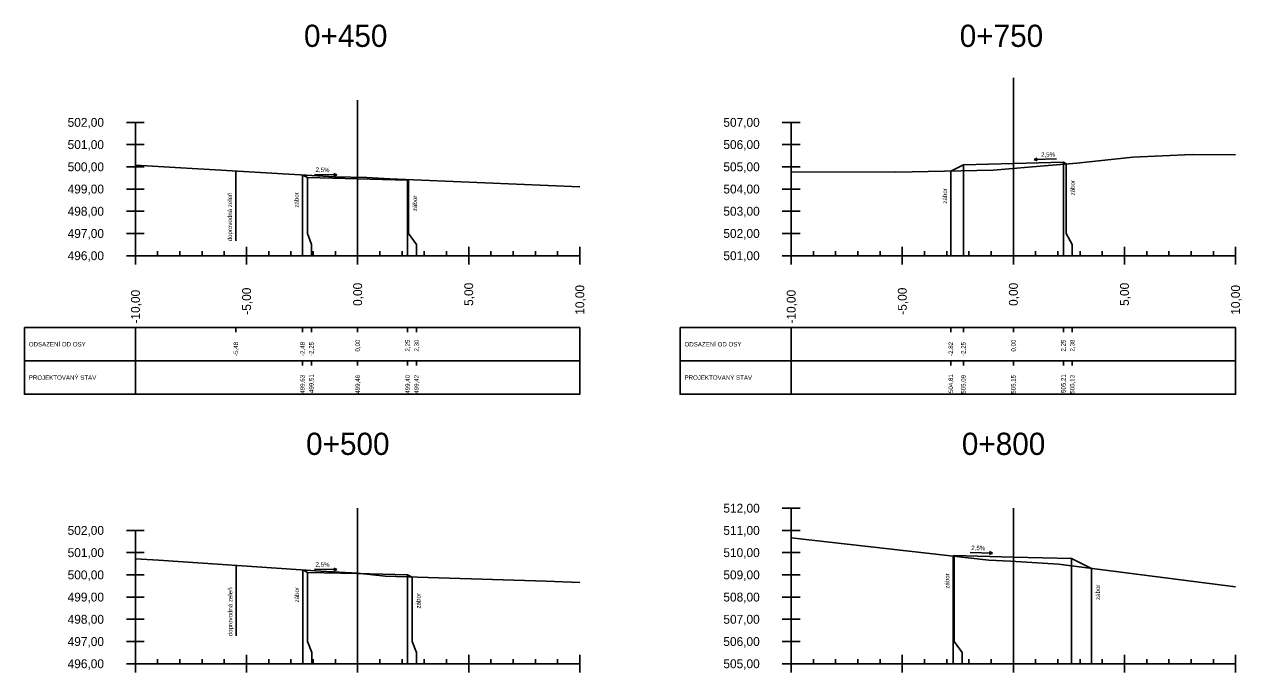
# Model space of a CAD drawing. Extents: x -631407 to -631215, y -1089700 to -1088598.
# Drawn here: x -631373.7 to -631319, y -1089386.7 to -1089357.5 of the extents above; entities that cross this region are included whole.
import ezdxf

# ---------------------------------------------------------------- set-up
doc = ezdxf.new("R2010")
doc.units = 0
for name, color, linetype in [('59', 7, 'Continuous'), ('NIVELETA_VYSKY', 7, 'Continuous'), ('REZ_BODY', 7, 'Continuous'), ('REZ_ODSTUPY', 7, 'Continuous'), ('REZ_POPIS', 7, 'Continuous'), ('REZ_RAMY', 7, 'Continuous'), ('REZ_STANICENI', 7, 'Continuous'), ('REZ_SVISLE', 7, 'Continuous'), ('REZ_TENKA', 7, 'Continuous'), ('REZ_TLUSTA', 7, 'Continuous'), ('TABULKA_POPIS', 7, 'Continuous'), ('TEREN', 7, 'Continuous'), ('zábor', 7, 'Continuous')]:
    doc.layers.add(name, color=color, linetype=linetype)

msp = doc.modelspace()

# ---------------------------------------------------------------- linework, layer by layer
at = {"layer": '59'}
for p, q in [((-631369.144, -1089361.911), (-631368.344, -1089361.911)), ((-631368.744, -1089361.911), (-631368.744, -1089367.911)), ((-631339.63, -1089361.911), (-631338.83, -1089361.911)), ((-631339.23, -1089361.911), (-631339.23, -1089367.911)), ((-631369.144, -1089362.911), (-631368.344, -1089362.911)), ((-631339.63, -1089362.911), (-631338.83, -1089362.911)), ((-631369.144, -1089363.911), (-631368.344, -1089363.911)), ((-631339.63, -1089363.911), (-631338.83, -1089363.911)), ((-631369.144, -1089364.911), (-631368.344, -1089364.911)), ((-631339.63, -1089364.911), (-631338.83, -1089364.911)), ((-631369.144, -1089365.911), (-631368.344, -1089365.911)), ((-631339.63, -1089365.911), (-631338.83, -1089365.911)), ((-631369.144, -1089366.911), (-631368.344, -1089366.911)), ((-631339.63, -1089366.911), (-631338.83, -1089366.911)), ((-631369.144, -1089367.911), (-631368.344, -1089367.911)), ((-631339.63, -1089367.911), (-631338.83, -1089367.911)), ((-631339.63, -1089379.273), (-631338.83, -1089379.273)), ((-631339.23, -1089379.273), (-631339.23, -1089386.273)), ((-631369.144, -1089380.273), (-631368.344, -1089380.273)), ((-631368.744, -1089380.273), (-631368.744, -1089386.273)), ((-631339.63, -1089380.273), (-631338.83, -1089380.273)), ((-631369.144, -1089381.273), (-631368.344, -1089381.273)), ((-631339.63, -1089381.273), (-631338.83, -1089381.273)), ((-631369.144, -1089382.273), (-631368.344, -1089382.273)), ((-631339.63, -1089382.273), (-631338.83, -1089382.273)), ((-631369.144, -1089383.273), (-631368.344, -1089383.273)), ((-631339.63, -1089383.273), (-631338.83, -1089383.273)), ((-631369.144, -1089384.273), (-631368.344, -1089384.273)), ((-631339.63, -1089384.273), (-631338.83, -1089384.273)), ((-631369.144, -1089385.273), (-631368.344, -1089385.273)), ((-631339.63, -1089385.273), (-631338.83, -1089385.273)), ((-631369.144, -1089386.273), (-631368.344, -1089386.273)), ((-631339.63, -1089386.273), (-631338.83, -1089386.273))]:
    msp.add_line(p, q, dxfattribs=at)
at = {"layer": 'REZ_RAMY'}
for p, q in [((-631373.744, -1089371.145), (-631373.744, -1089374.145)), ((-631368.744, -1089371.145), (-631368.744, -1089374.145)), ((-631364.227, -1089371.345), (-631364.227, -1089371.145)), ((-631361.227, -1089371.345), (-631361.227, -1089371.145)), ((-631360.827, -1089371.345), (-631360.827, -1089371.145)), ((-631358.744, -1089371.345), (-631358.744, -1089371.145)), ((-631356.494, -1089371.345), (-631356.494, -1089371.145)), ((-631356.094, -1089371.345), (-631356.094, -1089371.145)), ((-631344.23, -1089371.145), (-631344.23, -1089374.145)), ((-631339.23, -1089371.145), (-631339.23, -1089374.145)), ((-631332.048, -1089371.345), (-631332.048, -1089371.145)), ((-631331.48, -1089371.345), (-631331.48, -1089371.145)), ((-631329.23, -1089371.345), (-631329.23, -1089371.145)), ((-631326.98, -1089371.345), (-631326.98, -1089371.145)), ((-631326.58, -1089371.345), (-631326.58, -1089371.145)), ((-631373.744, -1089372.645), (-631348.744, -1089372.645)), ((-631361.227, -1089372.845), (-631361.227, -1089372.645)), ((-631360.827, -1089372.845), (-631360.827, -1089372.645)), ((-631358.744, -1089372.845), (-631358.744, -1089372.645)), ((-631356.494, -1089372.845), (-631356.494, -1089372.645)), ((-631356.094, -1089372.845), (-631356.094, -1089372.645)), ((-631344.23, -1089372.645), (-631319.23, -1089372.645)), ((-631332.048, -1089372.845), (-631332.048, -1089372.645)), ((-631331.48, -1089372.845), (-631331.48, -1089372.645)), ((-631329.23, -1089372.845), (-631329.23, -1089372.645)), ((-631326.98, -1089372.845), (-631326.98, -1089372.645)), ((-631326.58, -1089372.845), (-631326.58, -1089372.645))]:
    msp.add_line(p, q, dxfattribs=at)
for points in [[(-631373.744, -1089371.145), (-631373.744, -1089374.145), (-631348.744, -1089374.145), (-631348.744, -1089371.145)], [(-631344.23, -1089371.145), (-631344.23, -1089374.145), (-631319.23, -1089374.145), (-631319.23, -1089371.145)]]:
    msp.add_lwpolyline(points, close=True, dxfattribs=at)
at = {"layer": 'REZ_SVISLE'}
for points in [[(-631331.48, -1089363.818), (-631331.48, -1089366.911), (-631331.48, -1089367.411), (-631331.48, -1089367.911)], [(-631329.23, -1089363.762), (-631329.23, -1089366.911), (-631329.23, -1089367.411), (-631329.23, -1089367.911)], [(-631326.98, -1089363.705), (-631326.98, -1089366.911), (-631326.98, -1089367.411), (-631326.98, -1089367.911)], [(-631326.85, -1089363.783), (-631326.85, -1089366.911), (-631326.58, -1089367.411), (-631326.58, -1089367.911)], [(-631361.227, -1089364.282), (-631361.227, -1089366.911), (-631361.227, -1089367.411), (-631361.227, -1089367.911)], [(-631360.994, -1089364.398), (-631360.994, -1089366.911), (-631360.827, -1089367.411), (-631360.827, -1089367.911)], [(-631332.048, -1089364.102), (-631332.048, -1089366.911), (-631332.048, -1089367.411), (-631332.048, -1089367.911)], [(-631358.744, -1089364.454), (-631358.744, -1089366.911), (-631358.744, -1089367.411), (-631358.744, -1089367.911)], [(-631356.494, -1089364.511), (-631356.494, -1089366.911), (-631356.494, -1089367.411), (-631356.494, -1089367.911)], [(-631356.448, -1089364.488), (-631356.448, -1089366.911), (-631356.094, -1089367.411), (-631356.094, -1089367.911)], [(-631331.941, -1089381.43), (-631331.941, -1089385.273), (-631331.941, -1089385.773), (-631331.941, -1089386.273)], [(-631331.892, -1089381.406), (-631331.892, -1089385.273), (-631331.541, -1089385.773), (-631331.541, -1089386.273)], [(-631329.23, -1089381.472), (-631329.23, -1089385.273), (-631329.23, -1089385.773), (-631329.23, -1089386.273)], [(-631326.611, -1089381.538), (-631326.611, -1089385.273), (-631326.611, -1089385.773), (-631326.611, -1089386.273)], [(-631361.21, -1089382.051), (-631361.21, -1089385.273), (-631361.21, -1089385.773), (-631361.21, -1089386.273)], [(-631360.994, -1089382.159), (-631360.994, -1089385.273), (-631360.81, -1089385.773), (-631360.81, -1089386.273)], [(-631358.744, -1089382.215), (-631358.744, -1089385.273), (-631358.744, -1089385.773), (-631358.744, -1089386.273)], [(-631356.494, -1089382.272), (-631356.494, -1089385.273), (-631356.494, -1089385.773), (-631356.494, -1089386.273)], [(-631356.296, -1089382.371), (-631356.296, -1089385.273), (-631356.094, -1089385.773), (-631356.094, -1089386.273)], [(-631325.714, -1089381.986), (-631325.714, -1089385.273), (-631325.714, -1089385.773), (-631325.714, -1089386.273)]]:
    msp.add_lwpolyline(points, dxfattribs=at)
at = {"layer": 'REZ_TENKA'}
for p, q in [((-631367.744, -1089367.911), (-631367.744, -1089367.711)), ((-631366.744, -1089367.911), (-631366.744, -1089367.711)), ((-631365.744, -1089367.911), (-631365.744, -1089367.711)), ((-631364.744, -1089367.911), (-631364.744, -1089367.711)), ((-631362.744, -1089367.911), (-631362.744, -1089367.711)), ((-631361.744, -1089367.911), (-631361.744, -1089367.711)), ((-631360.744, -1089367.911), (-631360.744, -1089367.711)), ((-631359.744, -1089367.911), (-631359.744, -1089367.711)), ((-631357.744, -1089367.911), (-631357.744, -1089367.711)), ((-631356.744, -1089367.911), (-631356.744, -1089367.711)), ((-631355.744, -1089367.911), (-631355.744, -1089367.711)), ((-631354.744, -1089367.911), (-631354.744, -1089367.711)), ((-631352.744, -1089367.911), (-631352.744, -1089367.711)), ((-631351.744, -1089367.911), (-631351.744, -1089367.711)), ((-631350.744, -1089367.911), (-631350.744, -1089367.711)), ((-631349.744, -1089367.911), (-631349.744, -1089367.711)), ((-631338.23, -1089367.911), (-631338.23, -1089367.711)), ((-631337.23, -1089367.911), (-631337.23, -1089367.711)), ((-631336.23, -1089367.911), (-631336.23, -1089367.711)), ((-631335.23, -1089367.911), (-631335.23, -1089367.711)), ((-631333.23, -1089367.911), (-631333.23, -1089367.711)), ((-631332.23, -1089367.911), (-631332.23, -1089367.711)), ((-631331.23, -1089367.911), (-631331.23, -1089367.711)), ((-631330.23, -1089367.911), (-631330.23, -1089367.711)), ((-631328.23, -1089367.911), (-631328.23, -1089367.711)), ((-631327.23, -1089367.911), (-631327.23, -1089367.711)), ((-631326.23, -1089367.911), (-631326.23, -1089367.711)), ((-631325.23, -1089367.911), (-631325.23, -1089367.711)), ((-631323.23, -1089367.911), (-631323.23, -1089367.711)), ((-631322.23, -1089367.911), (-631322.23, -1089367.711)), ((-631321.23, -1089367.911), (-631321.23, -1089367.711)), ((-631320.23, -1089367.911), (-631320.23, -1089367.711)), ((-631367.744, -1089386.273), (-631367.744, -1089386.073)), ((-631366.744, -1089386.273), (-631366.744, -1089386.073)), ((-631365.744, -1089386.273), (-631365.744, -1089386.073)), ((-631364.744, -1089386.273), (-631364.744, -1089386.073)), ((-631362.744, -1089386.273), (-631362.744, -1089386.073)), ((-631361.744, -1089386.273), (-631361.744, -1089386.073)), ((-631360.744, -1089386.273), (-631360.744, -1089386.073)), ((-631359.744, -1089386.273), (-631359.744, -1089386.073)), ((-631357.744, -1089386.273), (-631357.744, -1089386.073)), ((-631356.744, -1089386.273), (-631356.744, -1089386.073)), ((-631355.744, -1089386.273), (-631355.744, -1089386.073)), ((-631354.744, -1089386.273), (-631354.744, -1089386.073)), ((-631352.744, -1089386.273), (-631352.744, -1089386.073)), ((-631351.744, -1089386.273), (-631351.744, -1089386.073)), ((-631350.744, -1089386.273), (-631350.744, -1089386.073)), ((-631349.744, -1089386.273), (-631349.744, -1089386.073)), ((-631338.23, -1089386.273), (-631338.23, -1089386.073)), ((-631337.23, -1089386.273), (-631337.23, -1089386.073)), ((-631336.23, -1089386.273), (-631336.23, -1089386.073)), ((-631335.23, -1089386.273), (-631335.23, -1089386.073)), ((-631333.23, -1089386.273), (-631333.23, -1089386.073)), ((-631332.23, -1089386.273), (-631332.23, -1089386.073)), ((-631331.23, -1089386.273), (-631331.23, -1089386.073)), ((-631330.23, -1089386.273), (-631330.23, -1089386.073)), ((-631328.23, -1089386.273), (-631328.23, -1089386.073)), ((-631327.23, -1089386.273), (-631327.23, -1089386.073)), ((-631326.23, -1089386.273), (-631326.23, -1089386.073)), ((-631325.23, -1089386.273), (-631325.23, -1089386.073)), ((-631323.23, -1089386.273), (-631323.23, -1089386.073)), ((-631322.23, -1089386.273), (-631322.23, -1089386.073)), ((-631321.23, -1089386.273), (-631321.23, -1089386.073)), ((-631320.23, -1089386.273), (-631320.23, -1089386.073))]:
    msp.add_line(p, q, dxfattribs=at)
at = {"layer": 'REZ_TLUSTA'}
for p, q in [((-631329.23, -1089359.911), (-631329.23, -1089367.911)), ((-631358.744, -1089360.911), (-631358.744, -1089367.911)), ((-631368.744, -1089368.311), (-631368.744, -1089367.511)), ((-631363.744, -1089368.311), (-631363.744, -1089367.511)), ((-631358.744, -1089368.311), (-631358.744, -1089367.511)), ((-631353.744, -1089368.311), (-631353.744, -1089367.511)), ((-631348.744, -1089368.311), (-631348.744, -1089367.511)), ((-631339.23, -1089368.311), (-631339.23, -1089367.511)), ((-631334.23, -1089368.311), (-631334.23, -1089367.511)), ((-631329.23, -1089368.311), (-631329.23, -1089367.511)), ((-631324.23, -1089368.311), (-631324.23, -1089367.511)), ((-631319.23, -1089368.311), (-631319.23, -1089367.511)), ((-631368.744, -1089367.911), (-631348.744, -1089367.911)), ((-631339.23, -1089367.911), (-631319.23, -1089367.911)), ((-631358.744, -1089379.273), (-631358.744, -1089386.273)), ((-631329.23, -1089379.273), (-631329.23, -1089386.273)), ((-631368.744, -1089386.673), (-631368.744, -1089385.873)), ((-631368.744, -1089386.273), (-631348.744, -1089386.273)), ((-631363.744, -1089386.673), (-631363.744, -1089385.873)), ((-631358.744, -1089386.673), (-631358.744, -1089385.873)), ((-631353.744, -1089386.673), (-631353.744, -1089385.873)), ((-631348.744, -1089386.673), (-631348.744, -1089385.873)), ((-631339.23, -1089386.673), (-631339.23, -1089385.873)), ((-631339.23, -1089386.273), (-631319.23, -1089386.273)), ((-631334.23, -1089386.673), (-631334.23, -1089385.873)), ((-631329.23, -1089386.673), (-631329.23, -1089385.873)), ((-631324.23, -1089386.673), (-631324.23, -1089385.873)), ((-631319.23, -1089386.673), (-631319.23, -1089385.873))]:
    msp.add_line(p, q, dxfattribs=at)
at = {"layer": 'TEREN'}
for points in [[(-631368.744, -1089363.842), (-631367.727, -1089363.9), (-631359.786, -1089364.366), (-631358.335, -1089364.399), (-631357.29, -1089364.452), (-631348.744, -1089364.812)], [(-631339.23, -1089364.136), (-631334.515, -1089364.155), (-631330.134, -1089364.06), (-631327.67, -1089363.846), (-631326.376, -1089363.747), (-631323.846, -1089363.476), (-631321.182, -1089363.354), (-631319.23, -1089363.366)], [(-631332.048, -1089364.102), (-631331.48, -1089363.818), (-631329.23, -1089363.762), (-631326.98, -1089363.705), (-631326.85, -1089363.783)], [(-631361.227, -1089364.282), (-631360.994, -1089364.398), (-631358.744, -1089364.454), (-631356.494, -1089364.511), (-631356.448, -1089364.488)], [(-631339.23, -1089380.6), (-631330.337, -1089381.613), (-631329.357, -1089381.651), (-631327.2, -1089381.797), (-631319.23, -1089382.811)], [(-631368.744, -1089381.546), (-631367.701, -1089381.606), (-631360.395, -1089382.107), (-631358.744, -1089382.19), (-631357.503, -1089382.334), (-631350.255, -1089382.552), (-631348.744, -1089382.61)], [(-631331.941, -1089381.43), (-631331.892, -1089381.406), (-631329.23, -1089381.472), (-631326.611, -1089381.538), (-631325.714, -1089381.986)], [(-631361.21, -1089382.051), (-631360.994, -1089382.159), (-631358.744, -1089382.215), (-631356.494, -1089382.272), (-631356.296, -1089382.371)]]:
    msp.add_lwpolyline(points, dxfattribs=at)
at = {"layer": 'zábor'}
for p, q in [((-631328.297, -1089363.582), (-631328.16, -1089363.517)), ((-631328.297, -1089363.582), (-631327.289, -1089363.557)), ((-631328.297, -1089363.582), (-631328.157, -1089363.64)), ((-631364.227, -1089364.105), (-631364.227, -1089367.24)), ((-631359.677, -1089364.275), (-631360.685, -1089364.25)), ((-631359.677, -1089364.275), (-631359.816, -1089364.333)), ((-631359.677, -1089364.275), (-631359.813, -1089364.21)), ((-631330.163, -1089381.293), (-631331.171, -1089381.267)), ((-631330.163, -1089381.293), (-631330.302, -1089381.35)), ((-631330.163, -1089381.293), (-631330.299, -1089381.228)), ((-631364.21, -1089381.845), (-631364.21, -1089385.009)), ((-631359.677, -1089382.036), (-631360.685, -1089382.011)), ((-631359.677, -1089382.036), (-631359.816, -1089382.093)), ((-631359.677, -1089382.036), (-631359.813, -1089381.971))]:
    msp.add_line(p, q, dxfattribs=at)

# ---------------------------------------------------------------- texts
at = {"layer": 'NIVELETA_VYSKY'}
for s, p in [('499,63', (-631361.127, -1089374.121)), ('499,51', (-631360.727, -1089374.088)), ('499,46', (-631358.644, -1089374.121)), ('499,40', (-631356.394, -1089374.121)), ('499,42', (-631355.994, -1089374.121)), ('504,81', (-631331.948, -1089374.088)), ('505,09', (-631331.38, -1089374.121)), ('505,15', (-631329.13, -1089374.121)), ('505,21', (-631326.88, -1089374.088)), ('505,13', (-631326.48, -1089374.121))]:
    msp.add_text(s, height=0.2, rotation=90, dxfattribs=at).set_placement(p)
at = {"layer": 'REZ_BODY'}
for s, p in [('-5,48', (-631364.127, -1089372.422)), ('-2,48', (-631361.127, -1089372.422)), ('-2,25', (-631360.727, -1089372.422)), ('0,00', (-631358.644, -1089372.224)), ('2,25', (-631356.394, -1089372.224)), ('2,30', (-631355.994, -1089372.224)), ('-2,82', (-631331.948, -1089372.422)), ('-2,25', (-631331.38, -1089372.422)), ('0,00', (-631329.13, -1089372.224)), ('2,25', (-631326.88, -1089372.224)), ('2,38', (-631326.48, -1089372.224))]:
    msp.add_text(s, height=0.2, rotation=90, dxfattribs=at).set_placement(p)
at = {"layer": 'REZ_ODSTUPY'}
for s, p in [('0,00', (-631358.544, -1089370.17)), ('5,00', (-631353.544, -1089370.17)), ('10,00', (-631348.544, -1089370.567)), ('0,00', (-631329.03, -1089370.17)), ('5,00', (-631324.03, -1089370.17)), ('10,00', (-631319.03, -1089370.567)), ('-10,00', (-631368.544, -1089370.963)), ('-5,00', (-631363.544, -1089370.567)), ('-10,00', (-631339.03, -1089370.963)), ('-5,00', (-631334.03, -1089370.567))]:
    msp.add_text(s, height=0.4, rotation=90, dxfattribs=at).set_placement(p)
at = {"layer": 'REZ_POPIS'}
for s, p in [('502,00', (-631371.796, -1089362.111)), ('507,00', (-631342.282, -1089362.111)), ('501,00', (-631371.796, -1089363.111)), ('506,00', (-631342.282, -1089363.111)), ('500,00', (-631371.796, -1089364.111)), ('505,00', (-631342.282, -1089364.111)), ('499,00', (-631371.796, -1089365.111)), ('504,00', (-631342.282, -1089365.111)), ('498,00', (-631371.796, -1089366.111)), ('503,00', (-631342.282, -1089366.111)), ('497,00', (-631371.796, -1089367.111)), ('502,00', (-631342.282, -1089367.111)), ('496,00', (-631371.796, -1089368.111)), ('501,00', (-631342.282, -1089368.111)), ('512,00', (-631342.282, -1089379.473)), ('502,00', (-631371.796, -1089380.473)), ('511,00', (-631342.282, -1089380.473)), ('501,00', (-631371.796, -1089381.473)), ('510,00', (-631342.282, -1089381.473)), ('500,00', (-631371.796, -1089382.473)), ('509,00', (-631342.282, -1089382.473)), ('499,00', (-631371.796, -1089383.473)), ('508,00', (-631342.282, -1089383.473)), ('498,00', (-631371.796, -1089384.473)), ('507,00', (-631342.282, -1089384.473)), ('497,00', (-631371.796, -1089385.473)), ('506,00', (-631342.282, -1089385.473)), ('496,00', (-631371.796, -1089386.473)), ('505,00', (-631342.282, -1089386.473))]:
    msp.add_text(s, height=0.4, dxfattribs=at).set_placement(p)
at = {"layer": 'REZ_STANICENI'}
for s, p in [('0+450', (-631361.158, -1089358.515)), ('0+750', (-631331.644, -1089358.515)), ('0+500', (-631361.063, -1089376.876)), ('0+800', (-631331.549, -1089376.876))]:
    msp.add_text(s, height=1, dxfattribs=at).set_placement(p)
at = {"layer": 'TABULKA_POPIS'}
for s, p in [('ODSAZENÍ OD OSY', (-631373.544, -1089371.995)), ('ODSAZENÍ OD OSY', (-631344.03, -1089371.995)), ('PROJEKTOVANÝ STAV', (-631373.544, -1089373.495)), ('PROJEKTOVANÝ STAV', (-631344.03, -1089373.495))]:
    msp.add_text(s, height=0.2, dxfattribs=at).set_placement(p)
at = {"layer": 'zábor'}
for s, rotation, p in [('2,5%', 1.4321, (-631327.98, -1089363.461)), ('2,5%', 358.5679, (-631360.641, -1089364.138)), ('zábor', 90, (-631332.218, -1089365.565)), ('zábor', 90, (-631326.467, -1089365.198)), ('doprovodná zeleň', 90, (-631364.395, -1089367.264)), ('zábor', 90, (-631361.397, -1089365.745)), ('zábor', 90, (-631356.065, -1089365.902)), ('2,5%', 358.5679, (-631331.127, -1089381.155)), ('2,5%', 358.5679, (-631360.641, -1089381.899)), ('zábor', 90, (-631332.111, -1089382.894)), ('doprovodná zeleň', 90, (-631364.378, -1089385.034)), ('zábor', 90, (-631361.381, -1089383.514)), ('zábor', 90, (-631325.331, -1089383.4)), ('zábor', 90, (-631355.913, -1089383.785))]:
    msp.add_text(s, height=0.2, rotation=rotation, dxfattribs=at).set_placement(p)

doc.saveas('drawing.dxf')
